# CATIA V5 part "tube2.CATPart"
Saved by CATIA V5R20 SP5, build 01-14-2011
Part number: tube2
Bounding box of the stored display mesh (mm): x -29.961 to 29.961, y -29.961 to 877.5, z -30 to 30
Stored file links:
  M:\EU_thinkMotion\IAO_2010\iao\IAO_MMS_Groupe2\IAO_MMS_Groupe2\mayache\mayache\Pièces\tube2.CATPart
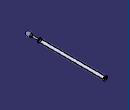
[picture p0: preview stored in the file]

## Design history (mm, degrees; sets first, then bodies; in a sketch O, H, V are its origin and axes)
Parameters
  rayboule = 30 mm
  raytubebase = 12 mm
  longtubebase = 100 mm
  raychambre = 20 mm
  longchambre = 750 mm
  ep = 5 mm
Body1 (main body)
  Sketch1 on yz-plane, origin (0, 0, 0), H (0, 1, 0), V (0, 0, 1)
    line L1 (0, 30) -> (0, -30)
    point P1 (0, 30)
    arc A1 centre (0, 0) radius 30 from (0, 30) to (0, -30) ccw
    distance O P1 = 30 {= rayboule}
    length L1 = 60 {= rayboule *2}
    radius A1 = 30 {= rayboule}
    coincidence: P1 V
    vertical: L1 V
  Shaft1: profile Sketch1, axis Sketch1.L1, angle 360
  Plane1: type Offset, RefPlane zx-plane, Offset 22.5 {= rayboule -(rayboule /4)}
  Body2
    Sketch2 on Plane1, origin (0, 22.5, 0), H (-1, 0, 0), V (0, 0, 1)
      circle A1 centre (0, 0) radius 12
      radius A1 = 12 {= raytubebase}
    Pad1: profile Sketch2, direction (0, 1, 0), length 100 {= longtubebase}
  Assemble1: tool Body2
  Fillet1: radius 10, on edge [face of Shaft1 from Sketch1.A1 | face of Pad1 from Sketch2.A1]
  Body3
    Sketch3 on end face of Pad1, origin (0, 122.5, 0), H (-1, 0, 0), V (0, 0, 1)
      circle A1 centre (0, 0) radius 25
      reference projected circle E1 centre (0, 0) radius 12 from edge [face of Pad1 from Sketch2.A1 | end face of Pad1]
      radius A1 = 25 {= raychambre+ep}
      concentricity: E1 A1
    Pad2: profile Sketch3, direction (0, 1, 0), length 750 {= longchambre}
    Shell1: ExtOffset 0, Face end face of Pad2, IntOffset 5 {= ep}
  Assemble2: tool Body3
  Fillet2: radius 10, on edge [face of Pad1 from Sketch2.A1 | start face of Pad2]
  Sketch4 on face of Pad2, origin (0, 872.5, 0), H (-1, 0, 0), V (0, 0, 1)
    circle A1 centre (0, 0) radius 25
    point P1 (25, 0)
    reference projected circle E1 centre (0, 0) radius 25 from edge [face of Pad2 from Sketch3.A1 | end face of Pad2]
    radius A1 = 25 {= raychambre +ep}
    coincidence: A1 P1, P1 H
    concentricity: A1 E1
  Pad3: profile Sketch4, direction (0, 1, 0), length 5 {= ep}
  Body4
    Sketch5 on end face of Pad3, origin (0, 877.5, 0), H (-1, 0, 0), V (0, 0, 1)
      circle A1 centre (0, 0) radius 12
      point P1 (12, 0)
      reference projected circle E1 centre (0, 0) radius 25 from edge [face of Pad3 | end face of Pad3]
      radius A1 = 12 {= raytubebase}
      coincidence: A1 P1, P1 H
      concentricity: A1 E1
    Pad4: profile Sketch5, direction (0, -1, 0), length 5 {= ep}
  Remove1: tool Body4
  Point1: type Center, Curve face of Shaft1 from Sketch1.A1
  Line1: type Normal, RefPoint Point1, RefSkin yz-plane, Start 0, End 20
